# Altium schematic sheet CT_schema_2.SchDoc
size 283 x 135 mm
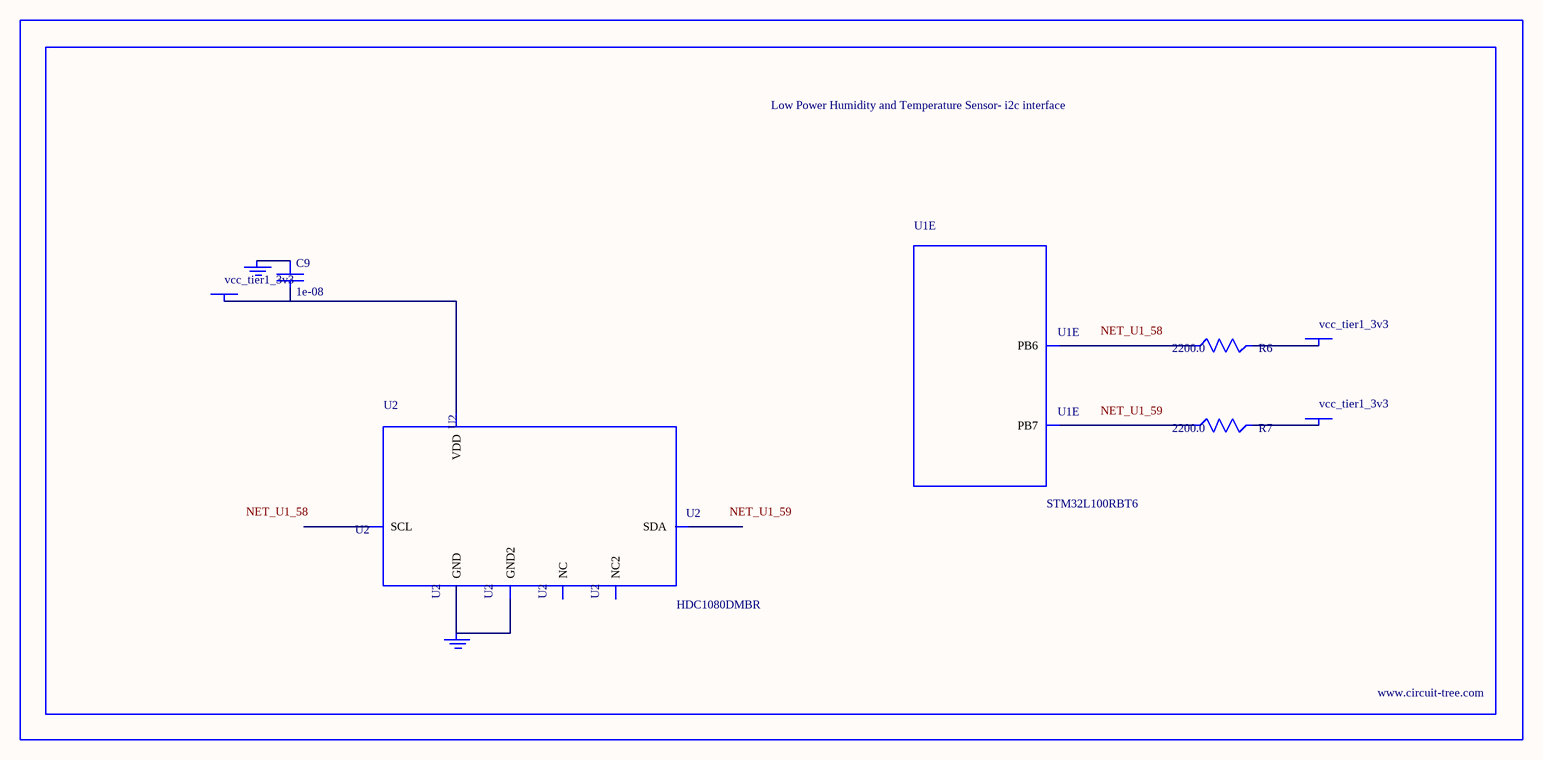
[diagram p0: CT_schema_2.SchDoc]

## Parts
BORDER1  (no value)
C9  1e-08  [C0402]
GND_INSTANCE_1_0  (no value)
GND_INSTANCE_1_1  (no value)
POWER_INSTANCE_1_0  vcc_tier1_3v3
POWER_INSTANCE_1_1  vcc_tier1_3v3
POWER_INSTANCE_1_2  vcc_tier1_3v3
R6  2200.0  [R0603]
R7  2200.0  [R0603]
U1  STM32L100RBT6  [LQFP64]  (part E of 7)
U2  HDC1080DMBR  [WSON-6]

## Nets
NetC9_1: C9.1 GND_INSTANCE_1_0.0(GND)
NetC9_2: C9.2 POWER_INSTANCE_1_0.0(PWR) U2.5(VDD)
NetGND_INSTANCE_1_1_0: GND_INSTANCE_1_1.0(GND) U2.2(GND) U2.PAD(GND2)
NetPOWER_INSTANCE_1_1_0: POWER_INSTANCE_1_1.0(PWR) R6.2
NetPOWER_INSTANCE_1_2_0: POWER_INSTANCE_1_2.0(PWR) R7.2
NetR6_1: R6.1 U1.58(PB6)
NetR7_1: R7.1 U1.59(PB7)

Not connected (* = marked no-connect by the designer): U2 1(SDA) 3(NC) 4(NC2) 6(SCL)

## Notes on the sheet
- Labels drawn without touching a wire or pin: NET_U1_58, NET_U1_59

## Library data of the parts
BORDER1 = BORDER_PAGE1
C9 = C0402C103K3RAC
GND_INSTANCE_1_0 GND_INSTANCE_1_1 = GND
POWER_INSTANCE_1_0-POWER_INSTANCE_1_2 = PWR
R6 R7 = RC0603JR-072K2L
